Omron Sysmac Studio project 通信测试4543x8 (Sysmac Studio 1.21.1.6, StandardProject)

# Controller new_Controller_0: NJ501-1500 version 1.14
Units and slaves: 电源 : NJ-Px3001; CPU : NJ501-1500; 0 [单元0] : CJ1W-SCU32 (J01)
Task PrimaryTask (priority 4, period or condition 1000): Program0

TYPE BD4523 : STRUCT
    PV : ARRAY[0..7] OF INT;  (* #1~8实际温度 *)
    ALM : UINT;  (* 报警状态 *)
    STA : UINT;  (* 模块故障 *)
    SV : ARRAY[0..7] OF INT;  (* #1~8设定温度 *)
    Pb : ARRAY[0..7] OF INT;  (* #1~8温度补偿 *)
    ErrorCNT : UINT;  (* 通信故障计数 *)
    TMP : ARRAY[0..19] OF INT;
END_STRUCT END_TYPE
TYPE BD4543 : STRUCT
    PV : ARRAY[0..15] OF INT;  (* #1~#16实际温度 *)
    RUNF : WORD;  (* 故障状态 *)
    ALF1 : WORD;  (* 报警1状态 *)
    ALF2 : WORD;  (* 报警2状态 *)
    ONB : WORD;  (* 温度控制启停位 *)
    ATUB : WORD;  (* PID自整定启停位 *)
    SV : ARRAY[0..15] OF INT;  (* 设定温度 *)
    Pb : ARRAY[0..15] OF INT;  (* PV值偏置 *)
    ErrorCNT : UINT;  (* 通信故障计算器 *)
    TMP : ARRAY[0..33] OF WORD;  (* 缓存，不要修改动 *)
END_STRUCT END_TYPE
TYPE BD4340 : STRUCT
    PV : ARRAY[0..15] OF INT;  (* #1~16实际温度 *)
    Pb : ARRAY[0..15] OF INT;  (* #1~16补偿温度 *)
    ErrorCNT : INT;  (* 通信故障计数 *)
END_STRUCT END_TYPE
TYPE BD4320 : STRUCT
    PV : ARRAY[0..7] OF INT;  (* #1~8实际温度 *)
    Pb : ARRAY[0..7] OF INT;  (* #1~8补偿温度 *)
    ErrorCNT : INT;  (* 通信故障计数 *)
END_STRUCT END_TYPE

VAR_GLOBAL
    FirstStartSW : BOOL;
    BD4523N : ARRAY[0..1] OF BD4523;  (* published *)
    BD4543N : ARRAY[0..7] OF BD4543;  (* published *)
    BD4340N : ARRAY[0..1] OF BD4340;  (* published *)
    BD4320N : ARRAY[0..1] OF BD4320;  (* published *)
    w0 : BOOL;
    A : UINT;
    B : UINT;
    C : UINT;
    PORT1 : _sPORT := (UnitNo := _CBU_No05, PhysicPortNo := 1);
    PORT2 : _sPORT := (UnitNo := _CBU_No05, PhysicPortNo := 2);
    P1_PmrExecuting : BOOL;  (* Port1宏协议运行中; at IOBus://rack#0/slot#0/P1_PmrSta/P1_PmrExecSta *)
    P1_SeqEndCmpFlg : BOOL;  (* Port1通信序列结束完成标志; at IOBus://rack#0/slot#0/P1_PmrSta/P1_PmrSeqEndSta *)
    P1_SeqAbtCmpFlg : BOOL;  (* Port1通信序列中止完成标志; at IOBus://rack#0/slot#0/P1_PmrSta/P1_PmrSeqAbtSta *)
END_VAR
VAR_GLOBAL RETAIN
    SenData AT %D10000 : ARRAY[0..100] OF WORD;
    RecivData AT %D10100 : ARRAY[0..100] OF WORD;
END_VAR

PROGRAM Program0
VAR
    BDCOMM : HelionCMM;
    ComErrCNT : UINT;
    PollTime : INT;
END_VAR
VAR_EXTERNAL
    w0 : BOOL;
END_VAR

(* Section 通信程序: ladder, written here as Structured Text *)

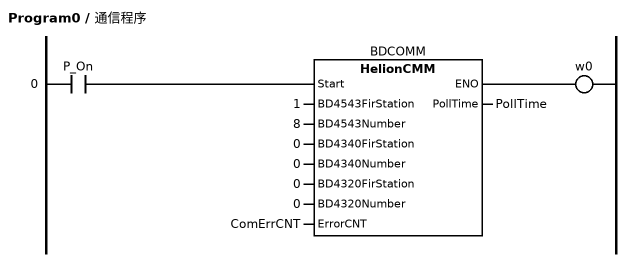
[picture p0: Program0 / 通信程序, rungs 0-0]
(* Rung 0 *)
BDCOMM(Start := P_On, BD4543FirStation := 1, BD4543Number := 8, BD4340FirStation := 0, BD4340Number := 0, BD4320FirStation := 0, BD4320Number := 0, ErrorCNT := ComErrCNT, PollTime => PollTime);
w0 := TRUE;
END_PROGRAM

FUNCTION_BLOCK HelionCMM
VAR
    a : INT;
    DELAY : INT;
    i : INT;
    j : INT;
    StartCom : BOOL;
    k : INT;
    Number : INT;
    STATUS : UINT;
    Station : INT;
    ET1 : TIME;
    EnStation1 : INT;
    EnStation2 : INT;
    EnStation3 : INT;
    T0_1S : BOOL;
    Q1 : BOOL;
    PBRD : ARRAY[0..50] OF BOOL;
    CTU_CYCLE : CTU;
    TON_Timer1 : TON;
    PollT : UINT;
    wTMP : WORD;
    done1 : BOOL;
    busy1 : BOOL;
    error1 : BOOL;
    errorId1 : WORD;
    errorIdex1 : DWORD;
    ExecPMCR_BD : ExecPMCR;
    ExecSta1 : BOOL;
    SeqNo : UINT;
    WARY : ARRAY[0..19] OF WORD;
    Nums : INT;
    Station1 : INT;
    Station2 : INT;
    Nums2 : INT;
    Nums1 : INT;
    Station0 : INT;
    Nums0 : INT;
    TimerReset : BOOL;
END_VAR
VAR_INPUT
    Start : BOOL;
    BD4543FirStation : INT;  (* BD4543首站号 *)
    BD4543Number : INT;  (* BD4543个数 *)
    BD4340FirStation : INT;  (* BD4340首站号 *)
    BD4340Number : INT;  (* BD4340个数 *)
    BD4320FirStation : INT;  (* BD4320首站号 *)
    BD4320Number : INT;  (* BD4320个数 *)
END_VAR
VAR_OUTPUT
    PollTime : INT;  (* 轮询周期 *)
END_VAR
VAR_IN_OUT
    ErrorCNT : UINT;  (* 通信错误计数 *)
END_VAR
VAR_EXTERNAL
    PORT1 : _sPORT;
    P1_PmrExecuting : BOOL;
END_VAR
VAR_EXTERNAL CONSTANT
    _Port_isAvailable : BOOL;
END_VAR
VAR_EXTERNAL
    P1_SeqEndCmpFlg : BOOL;
    BD4543N : ARRAY[0..7] OF BD4543;
    BD4340N : ARRAY[0..1] OF BD4340;
    BD4320N : ARRAY[0..1] OF BD4320;
    SenData : ARRAY[0..100] OF WORD;
    RecivData : ARRAY[0..100] OF WORD;
END_VAR
(*   通信开始   *)
IF STATUS = 0 AND StartCom THEN
	IF BD4543FirStation>=1 AND BD4543Number>0  THEN
		Number:=0;
		Station :=Station0;
	    STATUS := 1;
	ELSIF BD4340FirStation>=1 AND BD4340FirStation<=63 AND BD4340Number>0 THEN
		Number:=0;
		Station :=Station1;
	    STATUS := 30;
	ELSIF BD4320FirStation>=1 AND BD4320FirStation<=63 AND BD4320Number>0 THEN
		Number:=0;
		Station :=Station2;
	    STATUS := 35;
	END_IF;
END_IF;

IF STATUS=0 THEN
	TimerReset:=FALSE;
ELSE
		TimerReset:=TRUE;
END_IF;
T0_1S := Get100msClk();
CTU_CYCLE(CU := T0_1S, Reset := TimerReset, PV := 100, Q=>Q1, CV=>PollT);//轮询时间累计
PollTime:=PollT;

(*    通信初始化，延时启动   *)
TON_Timer1(In:=Start, PT:=T#200ms, Q=>StartCom, ET=>ET1);
IF StartCom=FALSE THEN
	STATUS :=0;
	Station0 :=BD4543FirStation;
	Nums0 :=BD4543Number;
	Station1 :=BD4340FirStation;
	Nums1 :=BD4340Number;
	Station2 :=BD4320FirStation;
	Nums2 :=BD4320Number;
	//FOR i :=0 TO 47  DO
	//	PBRD[i] :=FALSE;
	//END_FOR;
	Number :=0;
	ExecSta1 :=FALSE;
END_IF;

	ExecPMCR_BD(
		Execute:=ExecSta1, 
		Port:=PORT1, 
		SeqNo:=SeqNo, 
		SrcDat:=SenData[0], 
		DstDat:=RecivData[0], 
		Done=>done1, 
		Busy=>busy1, 
		Error=>error1, 
		ErrorID=>errorId1, 
		ErrorIDEx=>errorIdex1);

(*     状态1~10为BD4543通信    *)
//读BD4543V或BD4523V    Modbus地址#3000~#3052
IF STATUS=1 THEN
	DELAY :=DELAY+1;
	IF DELAY >2 THEN
		SenData[0]:=2;
		SenData[1]:=INT_TO_WORD(Station*256) ;
		SeqNo:=50;
		IF _Port_isAvailable=TRUE AND P1_PmrExecuting=FALSE AND ExecPMCR_BD.Busy=FALSE THEN
			ExecSta1:=TRUE;
			STATUS:=2;
		END_IF;
	END_IF;
END_IF;

IF STATUS=2 THEN
	IF ExecPMCR_BD.Done OR ExecPMCR_BD.Error THEN;
		ExecSta1 := FALSE;
	END_IF;
	IF ExecSta1=FALSE AND P1_PmrExecuting=FALSE THEN
		IF P1_SeqEndCmpFlg=TRUE THEN	
			FOR i :=0 TO 15 DO 
				j := i +1;
				BD4543N[Number].PV[i] := WORD_TO_INT(RecivData[j]);
			END_FOR;
			BD4543N[Number].RUNF := RecivData[16];
			BD4543N[Number].ALF1 := RecivData[17];
			BD4543N[Number].ALF2 := RecivData[18];
			k :=0;
			FOR i:=0 TO 33 DO
				j:=i+19;
				IF BD4543N[Number].TMP[i] <> RecivData[j] THEN
					k:=k+1;
					BD4543N[Number].TMP[i] := RecivData[j];
				END_IF;
			END_FOR;
			IF k<>0 THEN
				BD4543N[Number].ONB :=  RecivData[19];
				BD4543N[Number].ATUB :=  RecivData[20];
				FOR i :=0 TO 15 DO 
					j := i +21;
					BD4543N[Number].SV[i] := WORD_TO_INT(RecivData[j]);
					j := i +37;
					BD4543N[Number].Pb[i] := WORD_TO_INT(RecivData[j]);
				END_FOR;
			END_IF;
			STATUS := 3;
			DELAY :=0;
		ELSE	
			STATUS :=20;
		END_IF;
	END_IF;
END_IF;
//写BD4543V  #3019~#3052
IF STATUS=3 THEN
	DELAY:=DELAY+1;
	IF DELAY>2 THEN
		//检测是否需要写
		k:=0;
		IF  BD4543N[Number].ONB <> BD4543N[Number].TMP[0] THEN
			k:=k+1;
		END_IF;
		IF  BD4543N[Number].ATUB <> BD4543N[Number].TMP[1] THEN
			k:=k+1;
		END_IF;	
		FOR i:=0 TO 15 DO
			j:=i+2;
			IF BD4543N[Number].TMP[j] <> INT_TO_WORD(BD4543N[Number].SV[i])   THEN 
				k:=k+1;
			END_IF;
			j:=i+18;
			IF BD4543N[Number].TMP[j] <> INT_TO_WORD(BD4543N[Number].Pb[i])   THEN 
				k:=k+1;
			END_IF;
		END_FOR;
		//需要写BD4543
		IF k<>0 THEN
			SenData[0]:=36;
			SenData[1]:=INT_TO_WORD(Station*256) ;
			SeqNo:=51;
			SenData[2]:=BD4543N[Number].ONB;
			SenData[3]:=BD4543N[Number].ATUB;
			FOR i:=0 TO 15 DO
				j:=i+4;
				SenData[j]:=INT_TO_WORD(BD4543N[Number].SV[i]);
				j:=i+20;
				SenData[j]:=INT_TO_WORD(BD4543N[Number].Pb[i]);
			END_FOR;
			IF _Port_isAvailable=TRUE AND P1_PmrExecuting=FALSE AND ExecPMCR_BD.Busy=FALSE THEN
				ExecSta1:=TRUE;
				STATUS:=4;
			END_IF;
		ELSE
			STATUS:=5;
		END_IF;
	END_IF;
END_IF;

IF STATUS=4 THEN
	IF ExecPMCR_BD.Done OR ExecPMCR_BD.Error THEN;
		ExecSta1 := FALSE;
	END_IF;
	IF ExecSta1=FALSE AND P1_PmrExecuting=FALSE THEN
		IF P1_SeqEndCmpFlg=TRUE THEN
			FOR i :=0 TO 33 DO 
				j := i +2;
				BD4543N[Number].TMP[i] := SenData[j];
			END_FOR;
			STATUS := 5;
			DELAY :=0;
		ELSE
			STATUS :=20;
		END_IF;
	END_IF;
END_IF;
//清零通信故障计数器
IF STATUS=5 THEN
	STATUS:=21;
	BD4543N[Number].ErrorCNT:=0;
END_IF;
//通信故障计数器+1
IF STATUS=20 THEN
	PBRD[Number] :=FALSE;//标记
	STATUS:=21;
	BD4543N[Number].ErrorCNT:=BD4543N[Number].ErrorCNT+1;
	ErrorCNT:=ErrorCNT+1;
END_IF;
//切换
IF STATUS=21 THEN
	Number:=Number+1;
	Station:=Station+1;
	IF Number<Nums THEN
		STATUS:=1;
	ELSIF Station1>=1 AND Station1<=63 AND Nums1>0 THEN
		Number:=0;
		Station:=Station1;
	    STATUS := 30;
	ELSIF Station2>=1 AND Station2<=63 AND Nums2>0 THEN
		Number:=0;
		Station:=Station2;
	    STATUS := 35;
	END_IF;
END_IF;

(*    BD4340    *)
IF STATUS=30 THEN
	SenData[0]:=2;
	SenData[1]:=INT_TO_WORD(Station*256) ;
	SeqNo:=30;
	IF _Port_isAvailable=TRUE AND P1_PmrExecuting=FALSE AND ExecPMCR_BD.Busy=FALSE THEN
		ExecSta1:=TRUE;
		STATUS:=31;
	END_IF;
END_IF;

IF STATUS=31 THEN
	IF ExecPMCR_BD.Done OR ExecPMCR_BD.Error THEN;
		ExecSta1 := FALSE;
	END_IF;
	IF ExecSta1=FALSE AND P1_PmrExecuting=FALSE THEN
		IF P1_SeqEndCmpFlg=TRUE THEN
			FOR i :=0 TO 15 DO 
				j := i +1;
				BD4340N[Number].PV[i] := WORD_TO_INT(RecivData[j]) +BD4340N[Number].Pb[i] ;
			END_FOR;
			BD4340N[Number].ErrorCNT:=0;
			STATUS := 32;
		ELSE	
			BD4340N[Number].ErrorCNT:=BD4340N[Number].ErrorCNT+1;
			ErrorCNT:=ErrorCNT+1;
			STATUS :=32;
		END_IF;
	END_IF;
END_IF;
//切换
IF STATUS=32 THEN
	Number:=Number+1;
	Station:=Station+1;
	IF Number<Nums1 THEN
		STATUS:=30;
	ELSIF Station2>=1 AND Station2<=63 AND Nums2>0 THEN
		Number:=0;
		Station:=Station2;
	    STATUS := 35;
	END_IF;
END_IF;

(*   BD4320    *)
IF STATUS=35 THEN
	SenData[0]:=2;
	SenData[1]:=INT_TO_WORD(Station*256) ;
	SeqNo:=40;
	IF _Port_isAvailable=TRUE AND P1_PmrExecuting=FALSE AND ExecPMCR_BD.Busy=FALSE THEN
		ExecSta1:=TRUE;
		STATUS:=36;
	END_IF;
END_IF;

IF STATUS=36 THEN
	IF ExecPMCR_BD.Done OR ExecPMCR_BD.Error THEN;
		ExecSta1 := FALSE;
	END_IF;
	IF ExecSta1=FALSE AND P1_PmrExecuting=FALSE THEN
		IF P1_SeqEndCmpFlg=TRUE THEN	
			FOR i :=0 TO 7 DO 
				j := i +1;
				BD4320N[Number].PV[i] := WORD_TO_INT(RecivData[j]) +BD4320N[Number].Pb[i] ;
			END_FOR;
			BD4320N[Number].ErrorCNT:=0;
			STATUS := 37;
		ELSE
			BD4320N[Number].ErrorCNT:=BD4320N[Number].ErrorCNT+1;
			ErrorCNT:=ErrorCNT+1;
			STATUS :=37;
		END_IF;
	END_IF;
END_IF;
//切换
IF STATUS=37 THEN
	Number:=Number+1;
	Station:=Station+1;
	IF Number<Nums2 THEN
		STATUS:=35;
	ELSE		
	    STATUS := 0;
	END_IF;
END_IF;
END_FUNCTION_BLOCK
